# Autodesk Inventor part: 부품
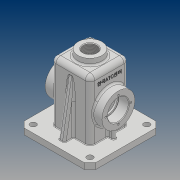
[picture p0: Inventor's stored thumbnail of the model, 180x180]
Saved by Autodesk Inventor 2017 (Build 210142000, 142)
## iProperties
Part Number: 부품
Material: 일반
Document SubType Name: Modeling
Designer: 20
Density: 1 g/cm^3
Appearance: 기본값
Mass: 293.223 g
Surface Area: 897.811 cm^2
Volume: 293.223 cm^3
Author: 20
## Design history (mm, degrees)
sketch "스케치1"
  geometry: L1 (-32.5, 32.5)-(32.5, 32.5); L2 (32.5, 32.5)-(32.5, -32.5); L3 (32.5, -32.5)-(-32.5, -32.5); L4 (-32.5, -32.5)-(-32.5, 32.5); L5 (-32.5, 32.5)-(32.5, -32.5); L6 (32.5, 32.5)-(-32.5, -32.5); 1 further point
  constraints: 12 end point, 2 midpoint, 2 parallel, 1 horizontal, 1 perpendicular
  dimensions: "d0" = 65 distance of L2.end L3.end; "d1" = 65 distance of L1.end L2.end
extrude "돌출1" new body sketch "스케치1" distance "d2" = 110; taper "d3" = 0 deg
fillet "모깎기1" dims "d4" = 8
fillet "모깎기2" dims "d5" = 8
sketch "스케치2"
  geometry: L1 (-60, -60)-(60, -60); L2 (60, -60)-(60, 60); L3 (60, 60)-(-60, 60); L4 (-60, 60)-(-60, -60); L5 (-60, -60)-(60, 60); L6 (60, -60)-(-60, 60); L7 (24.5, 32.5)-(-24.5, 32.5) reference; L8 (-32.5, 24.5)-(-32.5, -24.5) reference; L9 (-24.5, -32.5)-(24.5, -32.5) reference; L10 (32.5, -24.5)-(32.5, 24.5) reference; A1 r 8 centre (24.5, 24.5) between (32.5, 24.5) and (24.5, 32.5) reference; A2 r 8 centre (-24.5, 24.5) between (-24.5, 32.5) and (-32.5, 24.5) reference; A3 r 8 centre (-24.5, -24.5) between (-32.5, -24.5) and (-24.5, -32.5) reference; A4 r 8 centre (24.5, -24.5) between (24.5, -32.5) and (32.5, -24.5) reference; 1 further point
  constraints: 12 end point, 2 midpoint, 2 parallel, 1 horizontal, 1 perpendicular
  dimensions: "d7" = 120 distance of L3.end L2.end; "d8" = 120 distance of L1.end L2.end
extrude "돌출2" join sketch "스케치2" distance "d9" = 10; taper "d10" = 0 deg
chamfer "모따기1" distance "d11" = 10; stored, may be unused: second distance "d12" = 2, angle "d13" = 45 deg
sketch "스케치3"
  geometry: L1 (102, 74.5)-(102, -25.5) reference; C1 r 27.5 at (47, 24.5); 2 further points
  constraints: 1 centre point, 1 horizontal alignment, 1 midpoint
  dimensions: "d14" = 55 diameter of C1; "d15" = 55 distance from line of L1 C1.centre
extrude "돌출3" join sketch "스케치3" distance "d16" = 15; taper "d17" = 0 deg
sketch "스케치4"
  geometry: L1 (55, 50)-(55, -50) reference; 3 further points
  constraints: 1 horizontal alignment, 1 midpoint
  dimensions: "d18" = 76 distance from line of L1 point (-21, 0)
hole "구멍1" sketch "스케치4" at (-21, 0) diameter "d19" = 3.242; stored, may be unused: countersink angle "d23" = 90 deg, drill point angle "d25" = 118 deg; dims "d20" = 8, "d21" = 4, "d22" = 2, "d24" = 10
sketch "스케치5"
  geometry: C1 r 15 at (0, 0); A1 r 27.5 centre (0, 0) between (-12.49, 24.5) and (-12.49, -24.5) reference; 1 further point
  constraints: 1 centre point, 1 coincident
  dimensions: "d29" = 30 diameter of C1
extrude "돌출4" cut sketch "스케치5" stored distance "d30" = 15; taper "d31" = 0 deg
sketch "스케치7"
  geometry: C1 r 20 at (0, 0); 1 further point
  constraints: 1 centre point, 1 coincident
  dimensions: "d35" = 40 diameter of C1
extrude "돌출6" join sketch "스케치7" distance "d36" = 10; taper "d37" = 0 deg
hole "구멍2" diameter "d41" = 22.835; stored, may be unused: countersink angle "d45" = 90 deg, drill point angle "d47" = 118 deg; dims "d39" = 10, "d40" = 10, "d42" = 50, "d43" = 4, "d44" = 2, "d46" = 59.3
sketch "스케치10"
  geometry: L1 (-27.5, -27.5)-(27.5, -27.5); L2 (27.5, -27.5)-(27.5, 27.5); L3 (27.5, 27.5)-(-27.5, 27.5); L4 (-27.5, 27.5)-(-27.5, -27.5); L5 (-27.5, -27.5)-(27.5, 27.5); L6 (27.5, -27.5)-(-27.5, 27.5); 1 further point
  constraints: 12 end point, 2 midpoint, 2 parallel, 1 horizontal, 1 perpendicular
  dimensions: "d50" = 55 distance of L3.end L2.end; "d51" = 55 distance of L1.end L2.end
extrude "돌출7" cut sketch "스케치10" distance "d52" = 105; taper "d53" = 0 deg
fillet "모깎기3" dims "d54" = 3
fillet "모깎기4" dims "d55" = 3
sketch "스케치11"
  geometry: C1 r 15 at (0, 0) reference; C2 r 17.5 at (0, 0); 1 further point
  constraints: 1 centre point, 1 coincident
  dimensions: "d56" = 35 diameter of C2
extrude "돌출8" cut sketch "스케치11" distance "d57" = 17; taper "d58" = 0 deg
sketch "스케치14"
  geometry: L1 (50, 10)-(-50, 10) reference; L2 (-32.5, 10)-(-32.5, 102) reference; L3 (-48, 10)-(-32.5, 97.905); L4 (-60, 0)-(-60, 10) reference; 1 further point
  constraints: 2 end point, 2 point on line
  dimensions: "d59" = 12 distance from line of L4 L3.start; "d60" = 10 deg angle of L4 L3
feature "리브1" sketch "스케치14" dims "d61" = 1, "d62" = 10, "d63" = 0, "d64" = 0, "d65" = 1, "d66" = 1
sketch "스케치15"
  geometry: L1 (32.5, 3)-(42.5, 3); L2 (42.5, 3)-(42.5, -3); L3 (42.5, -3)-(32.5, -3); L4 (32.5, -3)-(32.5, 3); L5 (32.5, -24.5)-(32.5, 24.5) reference; 2 further points
  constraints: 8 end point, 2 parallel, 1 collinear, 1 horizontal, 1 midpoint, 1 perpendicular
  dimensions: "d74" = 6 distance of L1.end L2.end; "d75" = 3 distance from line of point (0, 0) L1; "d76" = 42.5 distance from line of L2 point (0, 0)
extrude "돌출9" join sketch "스케치15" stored distance "d77" = 17; taper "d78" = 0 deg
sketch "스케치16"
  geometry: C1 r 5 at (47.5, 47.5); 1 further point
  constraints: 1 centre point
  dimensions: "d79" = 10 diameter of C1; "d80" = 47.5 horizontal distance of C1.centre point (0, 0); "d81" = 47.5 horizontal distance of C1.centre point (0, 0)
extrude "돌출10" cut sketch "스케치16" stored distance "d82" = 17; taper "d83" = 0 deg
fillet "모깎기5" dims "d90" = 0.3
chamfer "모따기2" distance "d91" = 1; stored, may be unused: second distance "d92" = 2, angle "d93" = 45 deg
fillet "모깎기7" dims "d95" = 3
fillet "모깎기8" dims "d96" = 3
fillet "모깎기9" dims "d97" = 3
fillet "모깎기10" dims "d98" = 3
fillet "모깎기12" dims "d100" = 1
node "작업 평면1"
sketch "스케치17"
  geometry: L1 (-18, 44.5)-(-18, 4.5) reference; L2 (0, -8)-(91, -8) reference; 2 further points
  constraints: 1 other
  dimensions: "d103" = 26 distance from line of point (8, 24.5) L1; "d104" = 32.5 distance from line of L2 point (8, 24.5)
feature "엠보싱1" sketch "스케치17" dims "d7" = 120, "d8" = 120, "d105" = 0.5, "d106" = 0
fillet "모깎기14" dims "d107" = 3
feature "면 기울기2" dims angle "d108" = 5 deg
fillet "모깎기15" dims "d109" = 3
node "솔리드1"
pattern_circular "원형 패턴1" dims angle "d27" = 360 deg
mirror "미러1"
mirror "미러3"
mirror "미러4"
mirror "미러5"
pattern_linear "직사각형 패턴1" dims "d86" = 95, "d89" = 95
node "투영된 루프1"
